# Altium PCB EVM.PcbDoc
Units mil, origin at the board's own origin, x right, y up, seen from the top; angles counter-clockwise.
Board outline 2300 x 3975 mil, 4 copper layers (Top Layer L1, GND Plane L2, Vs Plane L3, Bottom Layer L4), stack 60.668 mil thick; 125 components, 52 nets, 281 pads, 154 vias.
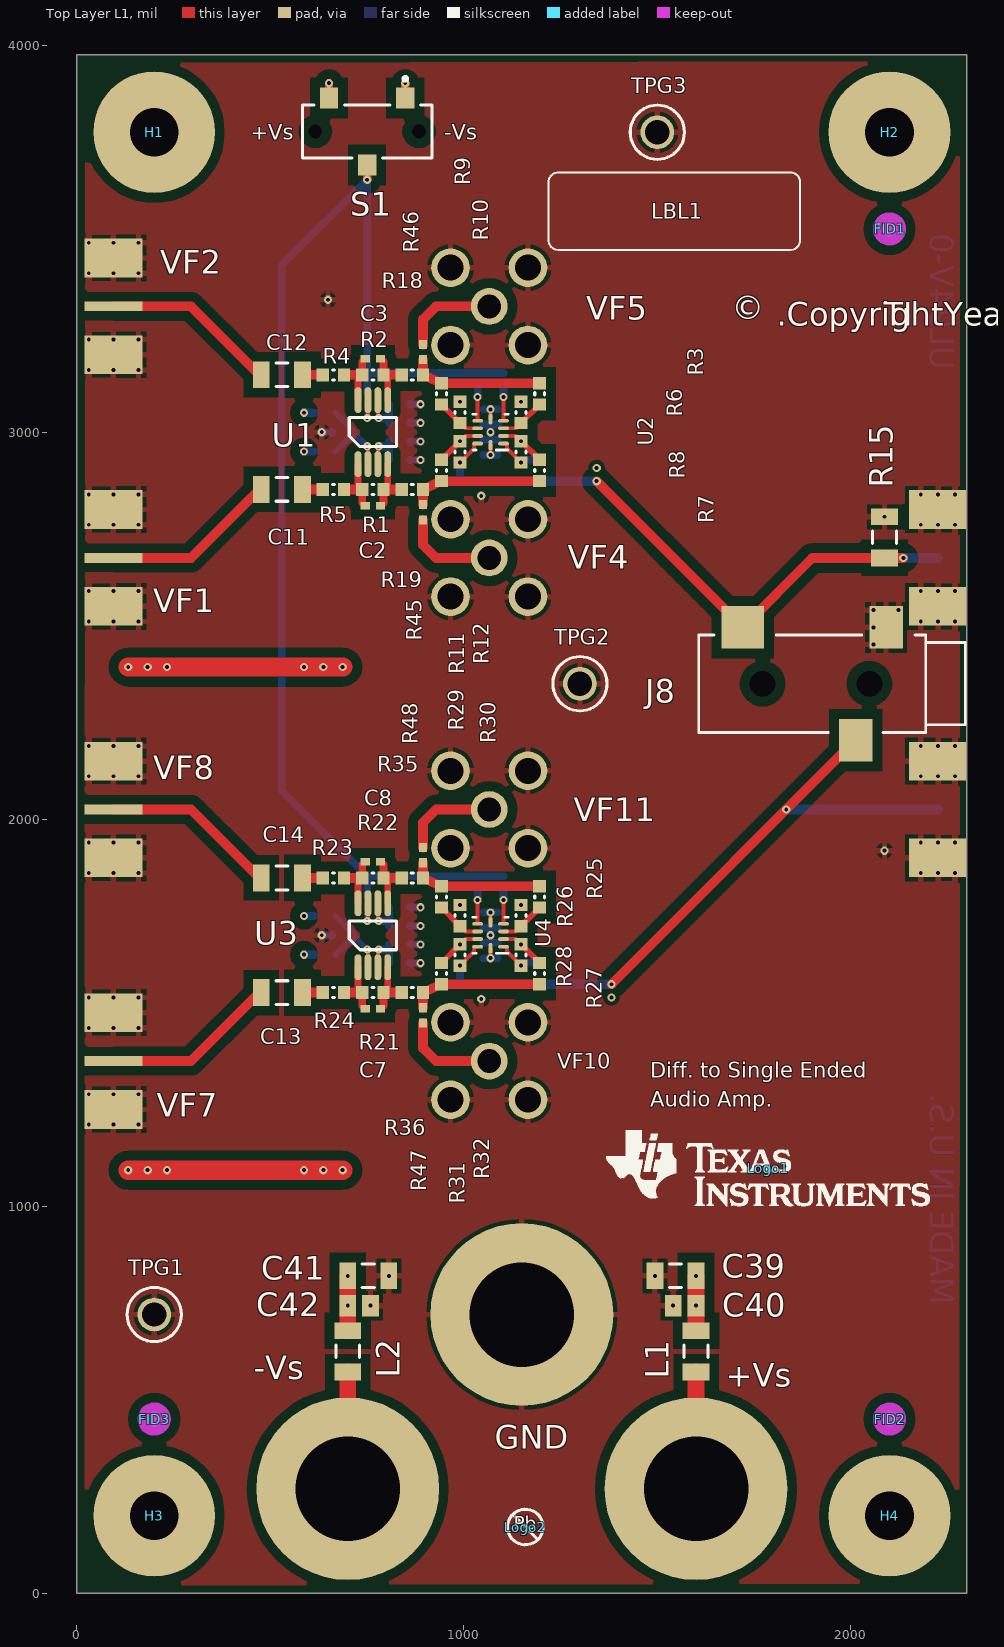
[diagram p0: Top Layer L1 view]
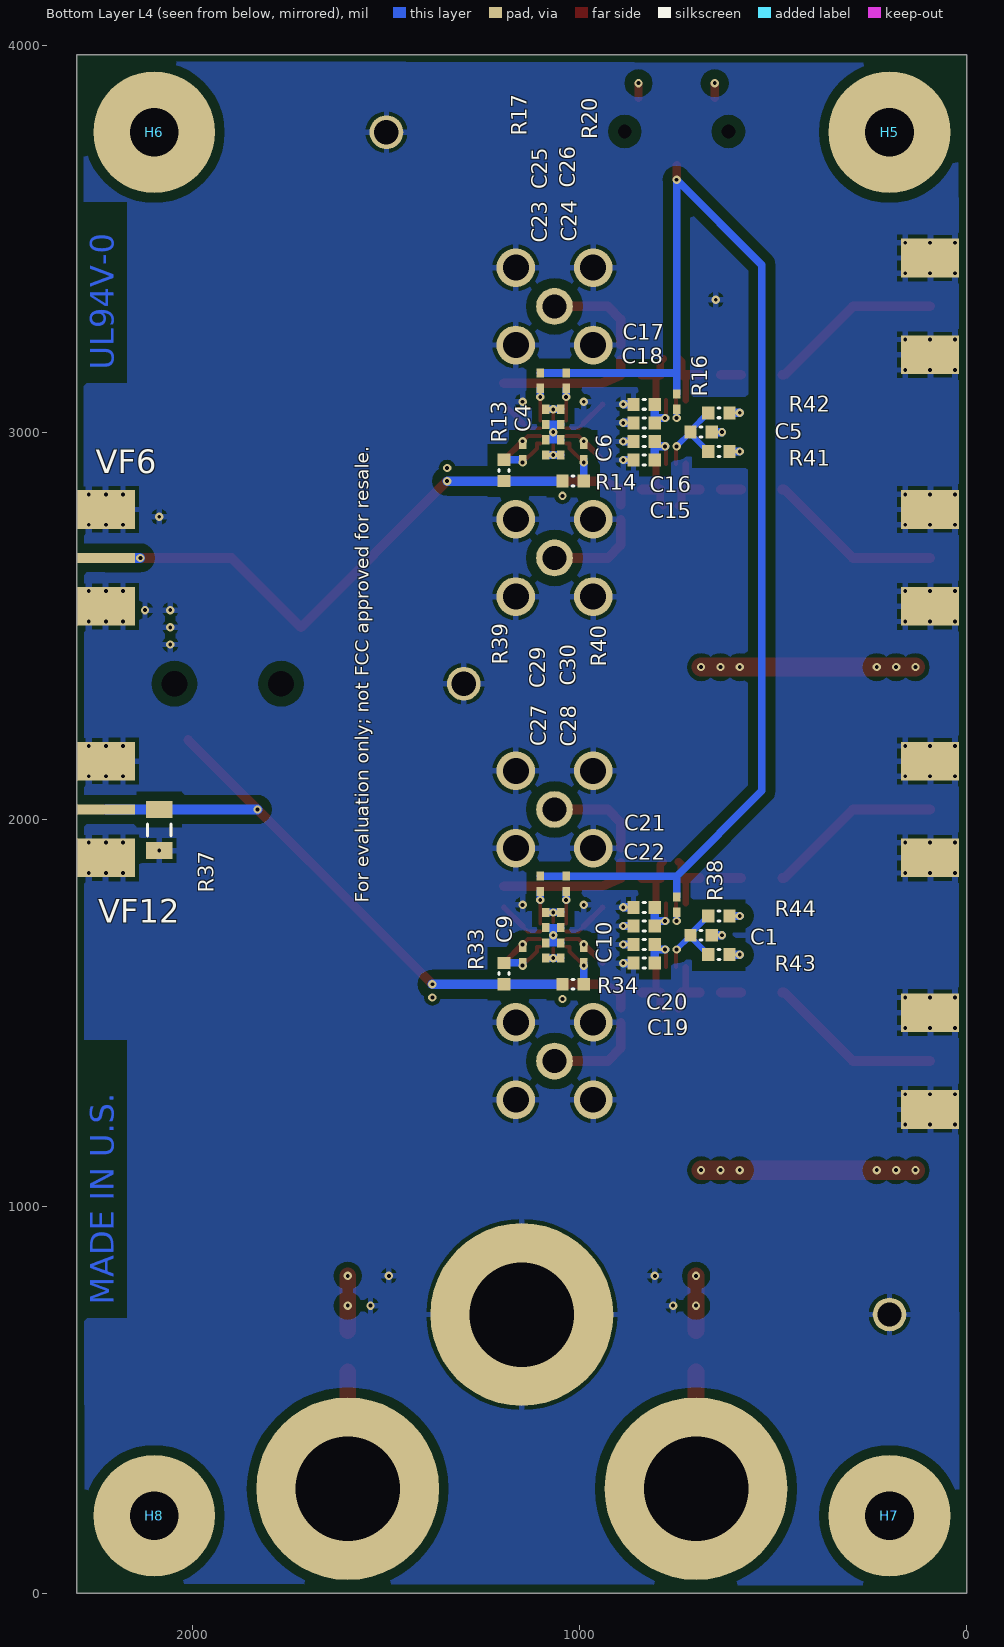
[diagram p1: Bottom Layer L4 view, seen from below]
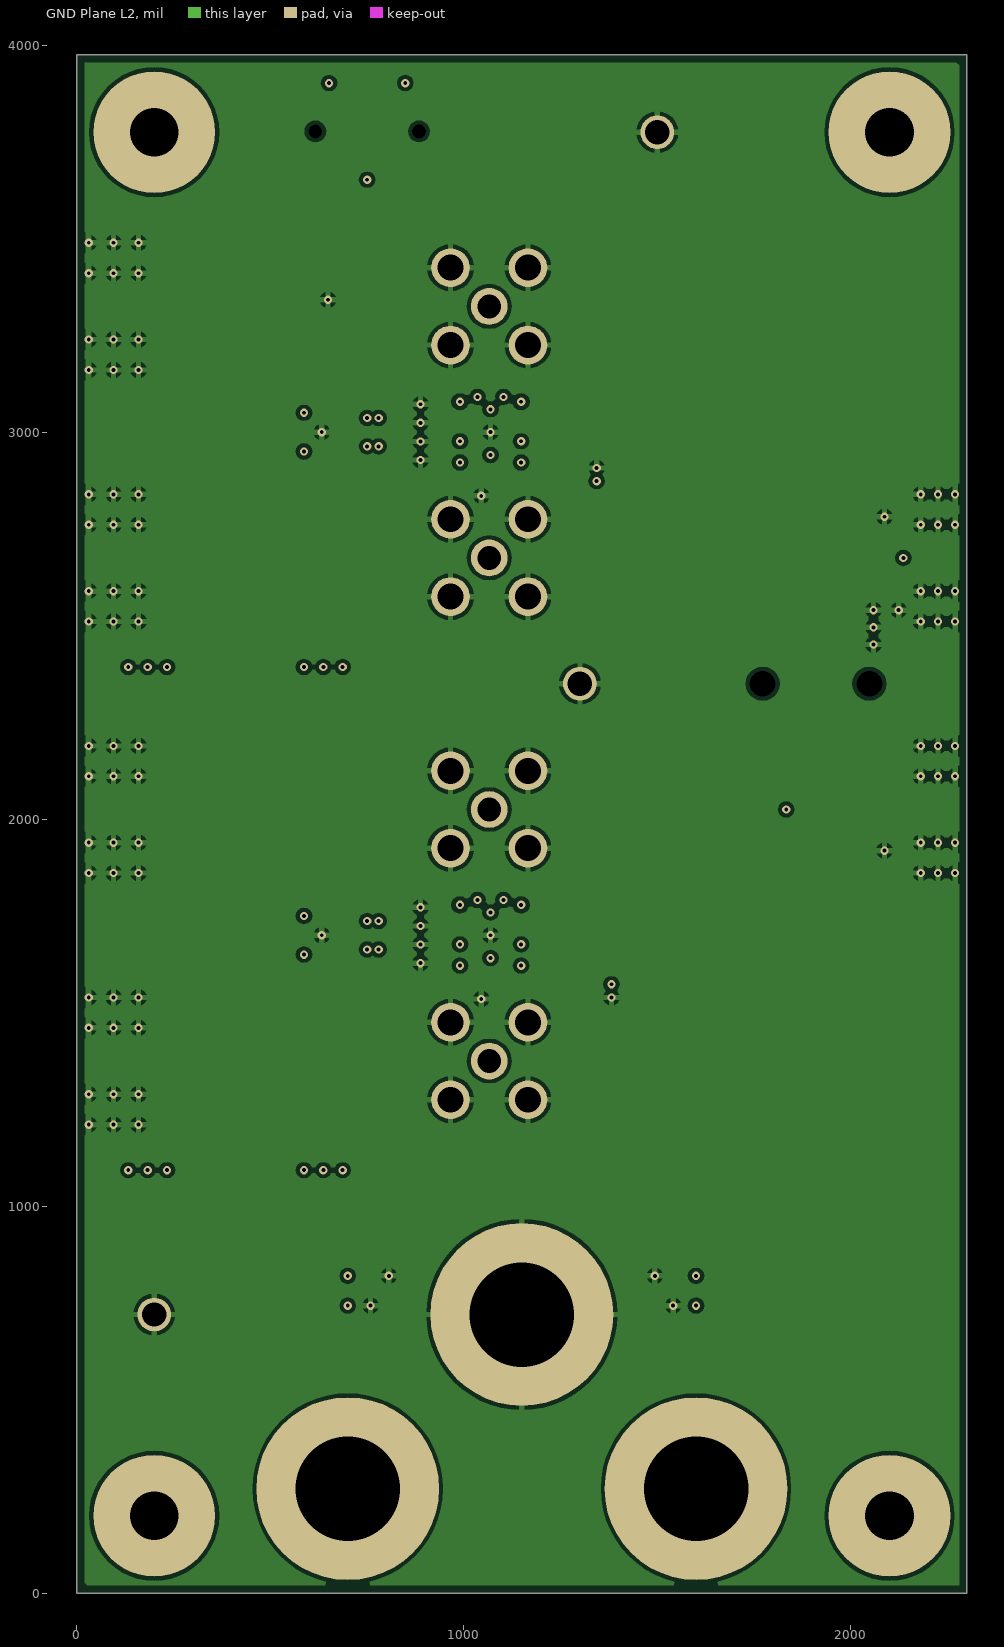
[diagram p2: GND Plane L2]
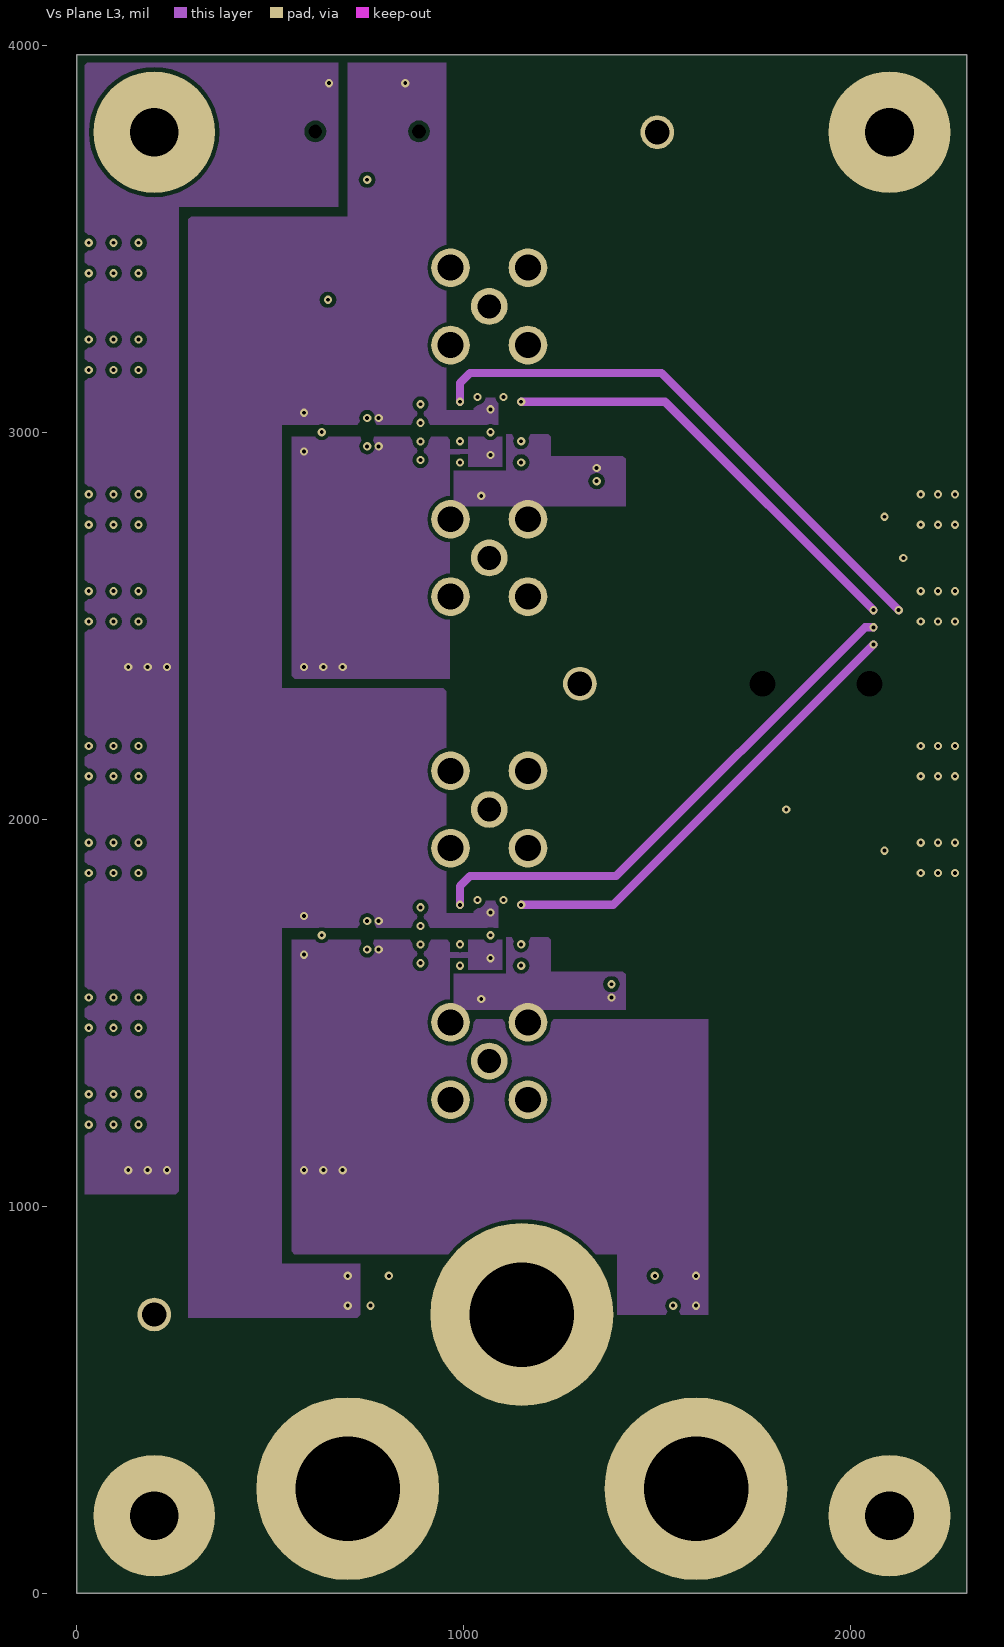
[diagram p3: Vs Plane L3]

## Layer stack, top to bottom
Top Solder: solder mask 0.4, Solder Resist, Dk 3.5
Top Layer L1: signal copper 1.417
Dielectric1: core 15, FR-406, Dk 4.8
GND Plane L2: signal copper 1.417
Dielectric3: prepreg 25, FR-406, Dk 4.2
Vs Plane L3: signal copper 1.417
Dielectric2: core 15, FR-406, Dk 4.2
Bottom Layer L4: signal copper 1.417
Bottom Solder: solder mask 0.4, Solder Resist, Dk 3.5

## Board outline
0,0 2300,0 2300,3975 0,3975

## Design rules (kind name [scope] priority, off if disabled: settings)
AcuteAngle [All] p1: minimum=4.50000000000000E+0001 checktracksonly=FALSE
AssemblyTestPointUsage [All] p1: valid=2
Clearance Clearance_1 [(InNamedPolygon('Top Layer L1-GND') OR InNamedPolygon('Bottom Layer L4-GND'))] p1: gap=25
Clearance Clearance_BoardEdge_MountingHoles [OnCopper and InComponentClass('Mounting Holes') vs IsKeepOut] p2: gap=40
Clearance Clearance_BoardEdge_Poly [OnCopper and InPoly vs IsKeepOut] p3: gap=25
Clearance Clearance_BoardEdge [OnCopper and Not InComponentClass('Logo') and not InComponentClass('FiducialMark') and not InRegion(1000,500,4000,800) and Not IsKeepout vs IsKeepOut] p4: gap=75
Clearance Clearance_Poly [InPolygon] p5: gap=10
Clearance [All] p6: gap=7.87
ComponentClearance ComponentClearance_Shunt [InComponentClass('Header') vs InComponentClass('Shunt')] p1: gap=0 collisioncheckmode=3 verticalgap=0 showdistances=FALSE
ComponentClearance ComponentClearance_MountingHoles_FiducialMarks [InComponentClass('Mounting Holes') vs InComponentClass('FiducialMark')] p2: gap=50 collisioncheckmode=3 verticalgap=10 showdistances=FALSE
ComponentClearance ComponentClearance_Logo [InComponentClass('Logo')] p3: gap=50 collisioncheckmode=3 verticalgap=10 showdistances=FALSE
ComponentClearance ComponentClearance_ScrewToNut [(HasFootprint('NY PMS 440 0025 PH')) vs (HasFootprint('Keystone_1902C'))] p4: gap=5 collisioncheckmode=3 verticalgap=10 showdistances=FALSE
ComponentClearance ComponentClearance_MountingHoles [InComponentClass('Mounting Holes')] p5: gap=125 collisioncheckmode=3 verticalgap=100000 showdistances=FALSE
ComponentClearance ComponentClearance_SmallPassives [HasFootprint('0201*') or HasFootprint('0402*') or HasFootprint('0508') or HasFootprint('0603*') or HasFootprint('0612') or HasFootprint('0805*') or HasFootprint('0815*') or HasFootprint('0830*') or HasFootprint('1206*') or HasFootprint('1210*') or HasFootprint('1808*') or HasFootprint('1812*') or HasFootprint('1825*') or HasFootprint('2010*') or HasFootprint('2220*') or HasFootprint('2225*') or HasFootprint('2512*') or HasFootprint('2728*') or HasFootprint('3518*') or HasFootprint('DGK0008A*') or HasFootprint('RUN0010A*') vs HasFootprint('0201*') or HasFootprint('0402*') or HasFootprint('0508') or HasFootprint('0603*') or HasFootprint('0612') or HasFootprint('0805*') or HasFootprint('0815*') or HasFootprint('0830*') or HasFootprint('1206*') or HasFootprint('1210*') or HasFootprint('1808*') or HasFootprint('1812*') or HasFootprint('1825*') or HasFootprint('2010*') or HasFootprint('2220*') or HasFootprint('2225*') or HasFootprint('2512*') or HasFootprint('2728*') or HasFootprint('3518*') or HasFootprint('DGK0008A*') or HasFootprint('RUN0010A*')] p6: gap=10 collisioncheckmode=3 verticalgap=10 showdistances=FALSE
ComponentClearance ComponentClearance_THtoSMT [IsThruComponent vs IsSMTComponent] p7: gap=30 collisioncheckmode=3 verticalgap=30 showdistances=FALSE
ComponentClearance ComponentClearance_THtoTH [IsThruComponent vs IsThruComponent] p8: gap=118.11 collisioncheckmode=3 verticalgap=30 showdistances=FALSE
ComponentClearance [All] p9: gap=10 collisioncheckmode=3 verticalgap=10 showdistances=FALSE
DiffPairsRouting [All] p1: maxlimit=100 minlimit=10 mostfreqgap=10 toplayer_minwidth=15 toplayer_maxwidth=15 toplayer_prefwidth=15 midlayer1_minwidth=15 midlayer1_maxwidth=15 midlayer1_prefwidth=15 midlayer2_minwidth=15 midlayer2_maxwidth=15 midlayer2_prefwidth=15 bottomlayer_minwidth=15 bottomlayer_maxwidth=15 bottomlayer_prefwidth=15 maxuncoupledlength=1000
FabricationTestPointUsage TestPointUsage [All] p1: valid=2 allowmultiple=FALSE
FabricationTestpoint Testpoint [All] p1: side=3 testpointundercomponent=TRUE minsize=40 maxsize=100 preferedsize=60 minholesize=0 maxholesize=40 preferedholesize=32 testpointgrid=1 allowsidetop=TRUE allowsidebottom=TRUE usegrid=TRUE gridtolerance=0.01
FanoutControl Fanout_LCC [IsLCC] p1: bgadir=Out bgaviamode=Centered fanoutstyle=Auto fanoutdirection=Alternating viagrid=1 // Fanout_LCC (Default Rule)
FanoutControl Fanout_BGA [IsBGA] p2: bgadir=Out bgaviamode=Centered fanoutstyle=Auto fanoutdirection=Alternating viagrid=1 // Fanout_BGA (Default Rule)
FanoutControl Fanout_Default [All] p4: bgadir=Out bgaviamode=Centered fanoutstyle=Auto fanoutdirection=Alternating viagrid=1 // Fanout_Default (Default Rule)
FanoutControl Fanout_Small [(CompPinCount < 5)] p5: bgadir=Out bgaviamode=Centered fanoutstyle=Auto fanoutdirection=OutThenIn viagrid=1 // Fanout_Small (Default Rule)
HoleSize [All] p1: absolutevalues=TRUE maxlimit=270 minlimit=8 maxpercent=80.000 minpercent=20.000
MinimumAnnularRing MinimumAnnularRing_ThermalPadVias [IsVia and InAnyComponent] p1: minimumring=5.91
MinimumAnnularRing [All] p2: minimumring=5.73
MinimumSolderMaskSliver MinimumSolderMaskSliver_Logo [InComponentClass('Logo') vs InComponentClass('Logo')] p1: minsoldermaskwidth=0.7
MinimumSolderMaskSliver [All] p2: minsoldermaskwidth=3.94
PlaneConnect [All] p1: planeconnectstyle=Relief reliefexpansion=10 reliefentries=4 reliefconductorwidth=10 reliefairgap=10
PolygonConnect PolygonConnect_1 [All vs IsNamedPolygon('Vs Plane L3+VS') Or  IsNamedPolygon('Vs Plane L3-VS') Or  IsNamedPolygon('Vs Plane L3+VS')  Or  IsNamedPolygon('Vs Plane GND')] p1: connectstyle=Direct reliefconductorwidth=10 reliefentries=4 polygonreliefangle="90 Angle" airgapwidth=10
PolygonConnect [All] p2: connectstyle=Relief reliefconductorwidth=15 reliefentries=4 polygonreliefangle="90 Angle" airgapwidth=10
RoutingVias ThermalPadVias [IsVia and InAnyComponent] p1: holewidth=7.87 width=19.68 viastyle="Through Hole" minholewidth=7.87 minwidth=19.68 maxholewidth=12.99 maxwidth=23.62
RoutingVias [All] p2: holewidth=16 width=34 viastyle="Through Hole" minholewidth=7.87 minwidth=21.46 maxholewidth=40 maxwidth=65
SMDToCorner [All] p1: distance=30000
SilkToSilkClearance SilkToSilkClearance_Pb-FreeLogo [(HasFootprint('Pb-Free_Overlay_Medium') OR HasFootprint('Pb-Free_Overlay_Small')) vs (HasFootprint('Pb-Free_Overlay_Medium') OR HasFootprint('Pb-Free_Overlay_Small'))] p1: silktosilkclearance=0
SilkToSilkClearance [All] p2: silktosilkclearance=5
SilkToSolderMaskClearance SilkscreenOverComponentPads [IsPad] p1: minsilkscreentomaskgap=5 clearancetoexposedcopper=TRUE
SolderMaskExpansion [All] p1: expansion=1.97
UnpouredPolygon [All] p1: allowunpoured=FALSE
Width [All] p1: maxlimit=100 minlimit=6 preferedwidth=10 checkconnectedcopper=TRUE
15 further rules are at their usual default settings.

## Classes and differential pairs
component class "Mounting Holes": H1 H2 H3 H4
component class Label: LBL1
component class AssemblyNote: ZZ1 ZZ2 ZZ3 ZZ4
component class FiducialMark: FID1 FID2 FID3
component class Logo: Logo1

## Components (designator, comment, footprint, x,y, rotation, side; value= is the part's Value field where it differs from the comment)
+Vs "SPC15363" Tenma_SPC15363 1600,270 r0 top
-Vs "SPC15182" Tenma_SPC15363 700,270 r0 top
C1 "C1608X7R1H104K" 0603L 687,1700 r180 bottom
C2 "" 0402L 765,2810 r180 top
C3 "" 0402L 765,3190 r180 top
C4 "" 0402L 1148,2949 r90 bottom
C5 "C1608X7R1H104K" 0603L 687,3000 r180 bottom
C6 "" 0402L 990,2949 r90 bottom
C7 "" 0402L 765,1510 r180 top
C8 "" 0402L 765,1890 r180 top
C9 "" 0402L 1148,1649 r90 bottom
C10 "" 0402L 990,1649 r90 bottom
C11 "" 1206L 530,2852 r180 top
C12 "" 1206L 530,3148 r180 top
C13 "" 1206L 530,1552 r180 top
C14 "" 1206L 530,1848 r180 top
C15 "C1608C0G1H102J" 0603L 834,2928 r0 bottom
C16 "06035A101JAT2A" 0603L 834,2976 r0 bottom
C17 "C1608C0G1H102J" 0603L 834,3072 r0 bottom
C18 "06035A101JAT2A" 0603L 834,3024 r0 bottom
C19 "C1608C0G1H102J" 0603L 834,1628 r0 bottom
C20 "06035A101JAT2A" 0603L 834,1676 r0 bottom
C21 "C1608C0G1H102J" 0603L 834,1772 r0 bottom
C22 "06035A101JAT2A" 0603L 834,1724 r0 bottom
C23 "C1005C0G1E102J" 0402L 1088,2960.69 r90 bottom
C24 "CC0402JRNPO9BN101" 0402L 1050,2960.69 r90 bottom
C25 "C1005C0G1E102J" 0402L 1088,3039.31 r270 bottom
C26 "CC0402JRNPO9BN101" 0402L 1050,3039.31 r270 bottom
C27 "C1005C0G1E102J" 0402L 1088,1660.68 r90 bottom
C28 "CC0402JRNPO9BN101" 0402L 1050,1660.68 r90 bottom
C29 "C1005C0G1E102J" 0402L 1088,1739.32 r270 bottom
C30 "CC0402JRNPO9BN101" 0402L 1050,1739.32 r270 bottom
C39 "GRM31CR61E106KA12L" 1206L 1546.85,820 r180 top
C40 "08055C104KAT2A" 0805L 1570.47,743 r180 top
C41 "GRM31CR61E106KA12L" 1206L 753.15,820 r180 top
C42 "08055C104KAT2A" 0805L 729.53,743 r180 top
FID1 "Fiducial" Fiducial10-20 2100,3525 r0 top
FID2 "Fiducial" Fiducial10-20 2100,450 r0 top
FID3 "Fiducial" Fiducial10-20 200,450 r0 top
GND "SPC15354" Tenma_SPC15354 1150,720 r180 top
H1 "NY PMS 440 0025 PH" "NY PMS 440 0025 PH" 200,3775 r0 top
H2 "NY PMS 440 0025 PH" "NY PMS 440 0025 PH" 2100,3775 r0 top
H3 "NY PMS 440 0025 PH" "NY PMS 440 0025 PH" 200,200 r0 top
H4 "NY PMS 440 0025 PH" "NY PMS 440 0025 PH" 2100,200 r0 top
H5 "1902C" Keystone_1902C 200,3775 r180 bottom
H6 "1902C" Keystone_1902C 2100,3775 r180 bottom
H7 "1902C" Keystone_1902C 200.36,200 r180 bottom
H8 "1902C" Keystone_1902C 2100.36,200 r180 bottom
J8 "SJ-3523-SMT" CUI_SJ-3523-SMT 1906,2350 r180 top
L1 "LQM31PN1R5MC0L" 1206L 1600,625 r90 top
L2 "LQM31PN1R5MC0L" 1206L 700,625 r90 top
LBL1 "Size: 0.65\" x 0.20 \"" Label_650x200 1544,3571 r0 top
Logo1 "Texas Instruments" TI_Stacked_Overlay_Small 1786,1098 r0 top
Logo2 "Pb-Free Symbol" Pb-Free_Overlay_Small 1159,171 r0 top
Logo3 "FCC disclaimer" FCC_disclaimer 4141,3143 r0 top
R1 "RT0603BRD071K11L" 0603L 765,2852 r0 top
R2 "RT0603BRD071K11L" 0603L 765,3148 r0 top
R3 "RT0603BRD071K11L" 0603L 1196,3099 r270 top
R4 "RT0603BRD07741RL" 0603L 663,3148 r0 top
R5 "RT0603BRD07741RL" 0603L 663,2852 r0 top
R6 "RT0603BRD071K11L" 0603L 1148,3051 r90 top
R7 "RT0603BRD071K11L" 0603L 1196,2901 r90 top
R8 "RT0603BRD071K11L" 0603L 1148,2949 r270 top
R9 "RT0603BRD071K11L" 0603L 942,3099 r270 top
R10 "RT0603BRD071K11L" 0603L 990,3051 r90 top
R11 "RT0603BRD071K11L" 0603L 942,2901 r90 top
R12 "RT0603BRD071K11L" 0603L 990,2949 r270 top
R13 "CRCW06031R00JNEA" 0603L 1196,2901 r270 bottom
R14 "CRCW06031R00JNEA" 0603L 1017.56,2873.44 r0 bottom
R15 "CRCW120632R4FKEA" 1206L 2087,2728.15 r270 top
R16 "CRCW040249R9FKED" 0402L 750.2,3079 r270 bottom
R17 "CRCW040249R9FKED" 0402L 1102.46,3133.23 r270 bottom
R18 "CRCW06030000Z0EA" 0603L 867,3148 r0 top
R19 "CRCW06030000Z0EA" 0603L 867,2852 r0 top
R20 "CRCW040249R9FKED" 0402L 1035.54,3133.23 r270 bottom
R21 "RT0603BRD071K11L" 0603L 765,1552 r0 top
R22 "RT0603BRD071K11L" 0603L 765,1848 r0 top
R23 "RT0603BRD07741RL" 0603L 663,1848 r0 top
R24 "RT0603BRD07741RL" 0603L 663,1552 r0 top
R25 "RT0603BRD071K11L" 0603L 1196,1799 r270 top
R26 "RT0603BRD071K11L" 0603L 1148,1751 r90 top
R27 "RT0603BRD071K11L" 0603L 1196,1601 r90 top
R28 "RT0603BRD071K11L" 0603L 1148,1649 r270 top
R29 "RT0603BRD071K11L" 0603L 942,1799 r270 top
R30 "RT0603BRD071K11L" 0603L 990,1751 r90 top
R31 "RT0603BRD071K11L" 0603L 942,1601 r90 top
R32 "RT0603BRD071K11L" 0603L 990,1649 r270 top
R33 "CRCW06031R00JNEA" 0603L 1196,1601 r270 bottom
R34 "CRCW06031R00JNEA" 0603L 1017.56,1573.44 r0 bottom
R35 "CRCW06030000Z0EA" 0603L 867,1848 r0 top
R36 "CRCW06030000Z0EA" 0603L 867,1552 r0 top
R37 "CRCW120632R4FKEA" 1206L 2087,1971.85 r90 bottom
R38 "CRCW040249R9FKED" 0402L 750.2,1779 r270 bottom
R39 "CRCW040249R9FKED" 0402L 1102.46,1833.23 r270 bottom
R40 "CRCW040249R9FKED" 0402L 1035.54,1833.23 r270 bottom
R41 "RT0603BRD071K11L" 0603L 641,2950 r180 bottom
R42 "RT0603BRD071K11L" 0603L 641,3050 r0 bottom
R43 "RT0603BRD071K11L" 0603L 641,1650 r180 bottom
R44 "RT0603BRD071K11L" 0603L 641,1750 r0 bottom
R45 "CRCW04020000Z0ED" 0402L 894.56,2793 r270 top
R46 "CRCW04020000Z0ED" 0402L 894.56,3207 r270 top
R47 "CRCW04020000Z0ED" 0402L 894.56,1493 r270 top
R48 "CRCW04020000Z0ED" 0402L 894.56,1907 r270 top
S1 "CL-SB-12B-01T" SW_CL-SB-12B-01 750.2,3777 r270 top
TPG1 "5011" Keystone5011 200,720 r0 top
TPG2 "5011" Keystone5011 1300,2350 r0 top
TPG3 "5011" Keystone5011 1500,3775 r0 top
U1 "THS4521IDGK" DGK0008A_N 765,3000 r90 top
U2 "OPA2836IRUNT" RUN0010A 1069,3000 r180 top
U3 "THS4521IDGK" DGK0008A_N 765,1700 r90 top
U4 "OPA2836IRUNT" RUN0010A 1069,1700 r180 top
VF1 "CONN_142-0711-821" CONN_142-0711-821 0,2675 r180 top
VF2 "CONN_142-0711-821" CONN_142-0711-821 0,3325 r180 top
VF4 "142-0701-201" Johnson_142-0701-20x 1065.68,2675 r0 top
VF5 "142-0701-201" Johnson_142-0701-20x 1065.68,3325 r0 top
VF6 "CONN_142-0711-821" CONN_142-0711-821 2320,2675 r0 bottom
VF7 "CONN_142-0711-821" CONN_142-0711-821 0,1375 r180 top
VF8 "CONN_142-0711-821" CONN_142-0711-821 0,2025 r180 top
VF10 "142-0701-201" Johnson_142-0701-20x 1065.68,1375 r180 top
VF11 "142-0701-201" Johnson_142-0701-20x 1065.68,2025 r180 top
VF12 "CONN_142-0711-821" CONN_142-0711-821 2320,2025 r0 bottom
ZZ1 "This Assembly Note is for PCB labels only" AssemblyNoteLabel 185,4438 r0 top
ZZ2 "These assemblies are ESD sensitive, ESD precautions shall be observed." AssemblyNote 185,4354.11 r0 top
ZZ3 "These assemblies must be clean and free from flux and all contaminants. Use of no clean flux is not acceptable." AssemblyNote 185,4265.56 r0 top
ZZ4 "These assemblies must comply with workmanship standards IPC-A-610 Class 2, unless otherwise specified." AssemblyNote 185,4177 r0 top

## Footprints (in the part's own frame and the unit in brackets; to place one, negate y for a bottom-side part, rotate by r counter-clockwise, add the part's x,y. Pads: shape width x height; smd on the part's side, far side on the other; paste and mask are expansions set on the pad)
0402L [mm] "0402 from SM-752 data"
  rect 0.6x0.5 smd: 1(-0.5,0) 2(0.5,0)
  body extent -0.55,-0.3 0.55,0.3, height 0.6
0603L [mm] "0603 from SM-752 data"
  rect 0.8x0.85 smd: 1(-0.7,0) 2(0.7,0)
  silkscreen extent -0.07,-0.33 0.07,0.33, body extent -0.87,-0.47 0.87,0.47, height 0.85
0805L [mm] "0805 from SM-752 data"
  rect 1.1x1.4 smd: 1(-0.75,0) 2(0.75,0)
  body extent -1.1,-0.72 1.1,0.72, height 1.1
1206L [mm] "1206 from SM-752 data"
  rect 1.1x1.75 smd: 1(-1.35,0) 2(1.35,0)
  silkscreen extent -0.4,-0.77 0.4,0.77, body extent -1.7,-0.9 1.7,0.9, height 1.35
AssemblyNote [mil] "Assembly Note"
AssemblyNoteLabel [mil] "Assembly Note for PCB Labels"
CONN_142-0711-821 [mil]
  rect 150x25 smd: 1(-95,0)
  rect 150x100 smd: 2(-95,125) 3(-95,-125)
  rect 150x100 smd far side: 4(-95,125) 5(-95,-125)
CUI_SJ-3523-SMT [mm] "CUI recommended land pattern Rev C CUI_SJ-3523-SMT_Datasheet.pdf"
  rect 2.2x2.8 smd: 1(-4.7,-3.7) 3(-2.7,3.7)
  rect 2.8x2.8 smd: 2(4.7,-3.7)
  round 0 hole 1.7 unplated: 4(-3.6,0) 5(3.4,0)
  silkscreen extent -9.9,-3.2 7.6,3.2, body extent -9.6,-4.5 7.4,4.5, height 5.12
DGK0008A_N [mm] "TSOP, 8-Leads, Body 3x3mm, Pitch 0.65mm, IPC Medium Density"
  oval 1.7x0.45 smd mask+0.05: 1(-2.1,0.975) 2(-2.1,0.325) 3(-2.1,-0.325) 4(-2.1,-0.975) 5(2.1,-0.975) 6(2.1,-0.325) 7(2.1,0.325) 8(2.1,0.975)
  silkscreen extent -0.95,-1.55 0.95,1.55, body extent -2.45,-1.5 2.45,1.5, height 0.94
FCC_disclaimer [mil]
Fiducial10-20 [mm]
  round 1 smd mask+0.5: 1(0,0)
  Top Layer L1 keep-out circle w1.178: c0,0 r0.5
Johnson_142-0701-20x [mil] "Johnson Components recommended land pattern"
  round 95 hole 62: 1(0,0)
  round 100 hole 67: 2(100,100) 3(100,-100) 4(-100,-100) 5(-100,100)
  body extent -156,-156 156,156, height 375
Keystone5011 [mil] "Keystone Multipurpose loops"
  round 87 hole 63: 1(0,0)
  silkscreen extent -70,-70 70,70, body extent -63,-63 63,62, height 319
Keystone_1902C [mil] "Hex Standoff, 4-40 threaded, nylon"
  round 1 on Mech4: 0(0,0)
  body extent -145,-126 146,126, height 501
Label_650x200 [mil] "Thermal Transfer Label"
  silkscreen extent -325,-100 325,100, body extent -326,-101 326,101, height 1
"NY PMS 440 0025 PH" [mm] "4-40 nylon screw and mounting hole"
  round 8 hole 3.2: 1(0,0)
  body extent -3.3,-3.3 3.3,3.3, height 2.69
Pb-Free_Overlay_Small [mil]
  silkscreen extent -46,-46 46,46
RUN0010A [mm]
  oval 0.7x0.25 smd: 1(-0.85,0.75) 2(-0.85,0.25) 3(-0.85,-0.25) 4(-0.85,-0.75) 6(0.85,-0.75) 7(0.85,-0.25) 8(0.85,0.25) 9(0.85,0.75)
  oval 0.25x0.7 smd: 5(0,-0.85) 10(0,0.85)
  silkscreen extent -1.15,-1.17 1.15,1.17, body extent -1.05,-1.05 1.05,1.05, height 0.81
SW_CL-SB-12B-01 [mm] "SMD, 3-Leads, Body 8.5x3.5mm, Pitch 2.5mm"
  rect 1.4x1.2 smd: 1(-2.2,2.5) 2(2.2,0) 3(-2.2,-2.5)
  round 0 hole 0.9 unplated: MH1(0,3.4) MH2(0,-3.4)
  silkscreen extent -3.57,-4.25 1.75,4.25, body extent -1.75,-4.25 1.75,4.25, height 5.5
Tenma_SPC15354 [mm] "Insulated Banana Jack, Black"
  round 12 hole 6.858: 1(0,0)
  body extent -6.3,-6.34 6.35,6.34, height 8.8
Tenma_SPC15363 [mm] "Insulated Banana Jack, Red"
  round 12 hole 6.858: 1(0,0)
  body extent -6.3,-6.34 6.35,6.34, height 8.8
TI_Stacked_Overlay_Small [mil]
  silkscreen extent -418,-98 418,98

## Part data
+Vs: "BANANA JACK, SOLDER LUG, RED, TH"
-Vs: library part SPC15363, "BANANA JACK, SOLDER LUG, GREEN, TH"
C1 C5: "CAP, CERM, 0.1 µF, 50 V, +/- 10%, X7R, 0603"
C2 C3 C4 C6 C7 C8 C9 C10 C11 C12 C13 C14: library part Capacitor, "CAP, CERM, xxxF, xxV, [TempCo], xx%, [PackageReference]"
C15 C17 C19 C21: "CAP, CERM, 1000 pF, 50 V, +/- 5%, C0G/NP0, 0603"
C16 C18 C20 C22: "CAP, CERM, 100 pF, 50 V, +/- 5%, C0G/NP0, 0603"
C23 C25 C27 C29: "CAP, CERM, 1000 pF, 25 V, +/- 5%, C0G/NP0, 0402"
C24 C26 C28 C30: "CAP, CERM, 100 pF, 50 V, +/- 5%, C0G/NP0, 0402"
C39 C41: "CAP, CERM, 10 µF, 25 V, +/- 10%, X5R, 1206"
C40 C42: "CAP, CERM, 0.1 µF, 50 V, +/- 10%, X7R, 0805"
FID1 FID2 FID3: "Fiducial mark.  There is nothing to buy or mount."
GND: "BANANA JACK, SOLDER LUG, BLACK, TH"
H1 H2 H3 H4: "Machine Screw, Round, #4-40 x 1/4, Nylon, Philips panhead"
H5 H6 H7 H8: "Standoff, Hex, 0.5\"L #4-40 Nylon"
J8: "Audio Jack, 3.5mm, Stereo, R/A, SMT"
L1 L2: "Inductor, Multilayer, Ferrite, 1.5 µH, 1 A, 0.17 ohm, SMD"
LBL1: library part THT-14-423-10, "Thermal Transfer Printable Labels, 0.650\" W x 0.200\" H - 10,000 per roll"
Logo1: library part TI_Logo, "Texas Instrument Corporate Signature"
Logo2: library part Pb-Free
Logo3: library part FCC_disclaimer, "FCC_disclaimer"
R1 R2 R3 R6 R7 R8 R9 R10 R11 R12 R21 R22 R25 R26 R27 R28 R29 R30 R31 R32 R41 R42 R43 R44: "RES, 1.11 k, 0.1%, 0.1 W, 0603"
R4 R5 R23 R24: "RES, 741, 0.1%, 0.1 W, 0603"
R13 R14 R33 R34: "RES, 1.0, 5%, 0.1 W, 0603"
R15 R37: "RES, 32.4, 1%, 0.25 W, 1206"
R16 R17 R20 R38 R39 R40: "RES, 49.9, 1%, 0.063 W, 0402"
R18 R19 R35 R36: "RES, 0, 5%, 0.1 W, 0603"
R45 R46 R47 R48: "RES, 0, 5%, 0.063 W, 0402"
S1: "Switch, Slide, SPDT, 0.2A, GULL, 12V, SMD"
TPG1 TPG2 TPG3: "Test Point, Multipurpose, Black, TH"
U1 U3: "VERY LOW POWER, NEGATIVE RAIL INPUT, RAIL-TO-RAIL OUTPUT, FULLY DIFFERENTIAL AMPLIFIER, DGK0008A"
U2 U4: "Dual, Very Low Power, Rail to Rail Out, Negative Rail In, VFB Operational Amplifier, 2.5 to 5.5 V, -40 to 85 degC, 10-pin QFN (RUN0010A), Green (RoHS & no Sb/Br)"
VF1 VF2 VF6 VF7 VF8 VF12: "CONNECTOR, SHEILDED, END LAUNCH JACK, GOLD PLATED, FOR 0.062 PCB, EDGE MOUNTED"
VF4 VF5 VF10 VF11: "Connector, TH, SMA"
ZZ1: library part AssemblyNoteLabel
ZZ2 ZZ3 ZZ4: library part AssemblyNote

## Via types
v1: diameter 21.46, hole 10, Top Layer L1 to Bottom Layer L4, tented both sides, 154 vias

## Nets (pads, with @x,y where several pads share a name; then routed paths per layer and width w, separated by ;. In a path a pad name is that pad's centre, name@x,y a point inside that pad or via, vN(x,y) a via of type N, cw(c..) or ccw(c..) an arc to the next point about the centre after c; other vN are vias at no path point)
+VS: C15.1 C16.1 C19.1 C20.1 C23.1 C24.1 C27.1 C28.1 C39.1 C40.1 L1.2 R41.2 R43.2 S1.3 U1.3 U2.10 U3.3 U4.10 | length 1711
  Top Layer L1 w9.84: v1(1069,1641) U4.10 ; v1(1069,2941) U2.10
  Top Layer L1 w10: U3.3 777.8,1661.32 v1(779.8,1663.32) ; U1.3 777.8,2961.32 v1(779.8,2963.32)
  Top Layer L1 w21.46: S1.3 v1(651.78,3901.91)
  Top Layer L1 w43.31: L1.2 v1(1600,743) v1(1600,820)
  Top Layer L1 w50: v1(133.04,1093) v1(686.96,1093) ; v1(133.04,2393) v1(686.96,2393)
  Bottom Layer L4 w19.68: C28.1 v1(1069,1641) C27.1 ; C24.1 v1(1069,2941) C23.1
  Bottom Layer L4 w21.46: v1(586.96,1650) R43.2 ; v1(586.96,2950) R41.2 ; v1(779.8,1663.32) C20.1@806.44,1663.32 ; v1(779.8,2963.32) C16.1@806.44,2963.32 ; C19.1 C20.1@806.44,1663.32 ; C20.1 C20.1@806.44,1663.32 ; C15.1 C16.1@806.44,2963.32 ; C16.1 C16.1@806.44,2963.32
  other v1: 183.04,1093 233.04,1093 586.96,1093 636.96,1093 183.04,2393 233.04,2393 586.96,2393 636.96,2393
-VS: C17.1 C18.1 C21.1 C22.1 C25.1 C26.1 C29.1 C30.1 C41.2 C42.2 L2.2 R42.1 R44.1 S1.1 U1.6 U2.5 U3.6 U4.5 | length 589
  Top Layer L1 w9.84: U4.5 v1(1069,1759) ; U2.5 v1(1069,3059)
  Top Layer L1 w10: U3.6 777.8,1738.68 v1(779.8,1736.68) ; U1.6 777.8,3038.68 v1(779.8,3036.68)
  Top Layer L1 w21.46: S1.1 v1(848.63,3901.91)
  Top Layer L1 w43.31: L2.2 v1(700,743) v1(700,820)
  Bottom Layer L4 w19.68: C30.1 v1(1069,1759) C29.1 ; C26.1 v1(1069,3059) C25.1
  Bottom Layer L4 w21.46: v1(586.96,1750) R44.1 ; v1(586.96,3050) R42.1 ; v1(779.8,1736.68) 806.44,1736.68 C22.1 ; v1(779.8,3036.68) 806.44,3036.68 C18.1 ; 806.44,1743.73 C21.1 ; 806.44,3043.73 C17.1
GND: C1.2 C5.2 C15.2 C16.2 C17.2 C18.2 C19.2 C20.2 C21.2 C22.2 C23.2 C24.2 C25.2 C26.2 C27.2 C28.2 C29.2 C30.2 C39.2 C40.2 C41.1 C42.1 GND.1 J8.1 R6.2 R10.2 R15.1 R26.2 R30.2 R37.1 TPG1.1 TPG2.1 TPG3.1 VF1.2 VF1.3 VF1.4 VF1.5 VF2.2 VF2.3 VF2.4 VF2.5 VF4.2 VF4.3 VF4.4 VF4.5 VF5.2 VF5.3 VF5.4 VF5.5 VF6.2 VF6.3 VF6.4 VF6.5 VF7.2 VF7.3 VF7.4 VF7.5 VF8.2 VF8.3 VF8.4 VF8.5 VF10.2 VF10.3 VF10.4 VF10.5 VF11.2 VF11.3 VF11.4 VF11.5 VF12.2 VF12.3 VF12.4 VF12.5 | length 5658.5
  Vs Plane L3 w21.46: v1(990,1778.56) 990,1827 1015.91,1852.91 1393.71,1852.91 2036.46,2495.67 v1(2058.46,2495.67) ; v1(990,3078.56) 990,3127 1015.91,3152.91 1510.76,3152.91 v1(2123.61,2540.06) ; v1(1148,1778.56) 1385.74,1778.56 v1(2058.46,2451.28) ; v1(1148,3078.56) 1519.96,3078.56 v1(2058.46,2540.06)
  Bottom Layer L4 w19.68: C28.2 1069,1680.37 ; C30.2 1069,1719.63 ; C24.2 1069,2980.37 ; C26.2 1069,3019.63 ; C27.2 1069,1680.37 ; C29.2 1069,1719.63 ; C23.2 1069,2980.37 ; C25.2 1069,3019.63 ; 1069,1680.37 v1(1069,1700) 1069,1719.63 ; 1069,2980.37 v1(1069,3000) 1069,3019.63
  Bottom Layer L4 w21.46: v1(632.96,1700) C1.2 ; v1(632.96,3000) C5.2 ; C19.2 v1(888.04,1628) ; C20.2 v1(888.04,1676) ; C22.2 v1(888.04,1724) ; C21.2 v1(888.04,1772) ; C15.2 v1(888.04,2928) ; C16.2 v1(888.04,2976) ; C18.2 v1(888.04,3024) ; C17.2 v1(888.04,3072)
  other v1: 759.06,743 1540.95,743 806.3,820 1493.7,820 30.73,1210.73 95,1210.73 159.27,1210.73 30.73,1289.27 95,1289.27 159.27,1289.27 30.73,1460.73 95,1460.73 159.27,1460.73 1045.12,1535.44 30.73,1539.27 95,1539.27 159.27,1539.27 1381.41,1539.44 30.73,1860.73 95,1860.73 159.27,1860.73 2180.73,1860.73 2225,1860.73 2269.27,1860.73 2087,1918.7 30.73,1939.27 95,1939.27 159.27,1939.27 2180.73,1939.27 2225,1939.27 2269.27,1939.27 30.73,2110.73 95,2110.73 159.27,2110.73 2180.73,2110.73 2225,2110.73 2269.27,2110.73 30.73,2189.27 95,2189.27 159.27,2189.27 2180.73,2189.27 2225,2189.27 2269.27,2189.27 30.73,2510.73 95,2510.73 159.27,2510.73 2180.73,2510.73 2225,2510.73 2269.27,2510.73 30.73,2589.27 95,2589.27 159.27,2589.27 2180.73,2589.27 2225,2589.27 2269.27,2589.27 30.73,2760.73 95,2760.73 159.27,2760.73 2180.73,2760.73 2225,2760.73 2269.27,2760.73 2087,2781.3 1045.12,2835.44 30.73,2839.27 95,2839.27 159.27,2839.27 2180.73,2839.27 2225,2839.27 2269.27,2839.27 1343.19,2907.44 30.73,3160.73 95,3160.73 159.27,3160.73 30.73,3239.27 95,3239.27 159.27,3239.27 649,3342 30.73,3410.73 95,3410.73 159.27,3410.73 30.73,3489.27 95,3489.27 159.27,3489.27
Net+Vs_1: +Vs.1 L1.1 | length 301.9
  Top Layer L1 w43.31: +Vs.1 L1.1
Net-Vs_1: -Vs.1 L2.1 | length 301.9
  Top Layer L1 w43.31: -Vs.1 L2.1
NetC1_1: C1.1 R43.1 R44.2 U3.2 | length 236.4
  Top Layer L1 w10: v1(750.2,1663.32) 752.2,1661.32 U3.2
  Bottom Layer L4 w15: R43.1 714.56,1696 C1.1 ; R44.2 714.56,1704 C1.1 ; v1(750.2,1663.32) 714.56,1698.97 C1.1
NetC2_1: C2.1 R1.2 R19.1 U1.4 | length 162
  Top Layer L1 w17.72: R1.2 803.39,2862.83 U1.4
  Top Layer L1 w19.68: C2.1 792.56,2817.87 R1.2
  Top Layer L1 w25: R1.2 R19.1
NetC2_2: C2.2 R1.1 R5.2 U1.1 | length 162
  Top Layer L1 w17.72: U1.1 726.61,2862.83 R1.1
  Top Layer L1 w19.68: R1.1 737.44,2817.87 C2.2
  Top Layer L1 w25: R5.2 R1.1
NetC3_1: C3.1 R2.2 R18.1 U1.5 | length 162
  Top Layer L1 w17.72: R2.2 803.39,3137.17 U1.5
  Top Layer L1 w19.68: C3.1 792.56,3182.13 R2.2
  Top Layer L1 w25: R2.2 R18.1
NetC3_2: C3.2 R2.1 R4.2 U1.8 | length 162
  Top Layer L1 w17.72: U1.8 726.61,3137.17 R2.1
  Top Layer L1 w19.68: R2.1 737.44,3182.13 C3.2
  Top Layer L1 w25: R4.2 R2.1
NetC4_1: C4.1 R8.2 R13.1 U2.1 | length 121.1
  Top Layer L1 w9.84: U2.1 1111.32,2970.47 1111.32,2958.12 v1(1148,2921.44)
  Bottom Layer L4 w19.68: C4.1@1148,2928.56 R13.1
NetC4_2: C4.2 R7.2 R8.1 U2.2 | length 119.1
  Top Layer L1 w9.84: U2.2 1134.4,2990.16 v1(1148,2976.56)
  Top Layer L1 w15: v1(1148,2976.56) R7.2
NetC5_1: C5.1 R41.1 R42.2 U1.2 | length 236.4
  Top Layer L1 w10: v1(750.2,2963.32) 752.2,2961.32 U1.2
  Bottom Layer L4 w15: R41.1 714.56,2996 C5.1 ; R42.2 714.56,3004 C5.1 ; v1(750.2,2963.32) 714.56,2998.97 C5.1
NetC6_1: C6.1 R12.2 R14.1 U2.9 | length 129
  Top Layer L1 w9.84: v1(990,2921.44) 1026.68,2958.12 1026.68,2970.47 U2.9
  Bottom Layer L4 w19.68: R14.1 C6.1
NetC6_2: C6.2 R11.2 R12.1 U2.8 | length 119.1
  Top Layer L1 w9.84: v1(990,2976.56) 1003.6,2990.16 U2.8
  Top Layer L1 w15: R11.2 v1(990,2976.56)
NetC7_1: C7.1 R21.2 R36.1 U3.4 | length 162
  Top Layer L1 w17.72: R21.2 803.39,1562.83 U3.4
  Top Layer L1 w19.68: C7.1 792.56,1517.87 R21.2
  Top Layer L1 w25: R21.2 R36.1
NetC7_2: C7.2 R21.1 R24.2 U3.1 | length 162
  Top Layer L1 w17.72: U3.1 726.61,1562.83 R21.1
  Top Layer L1 w19.68: R21.1 737.44,1517.87 C7.2
  Top Layer L1 w25: R24.2 R21.1
NetC8_1: C8.1 R22.2 R35.1 U3.5 | length 162
  Top Layer L1 w17.72: R22.2 803.39,1837.17 U3.5
  Top Layer L1 w19.68: C8.1 792.56,1882.13 R22.2
  Top Layer L1 w25: R22.2 R35.1
NetC8_2: C8.2 R22.1 R23.2 U3.8 | length 162
  Top Layer L1 w17.72: U3.8 726.61,1837.17 R22.1
  Top Layer L1 w19.68: R22.1 737.44,1882.13 C8.2
  Top Layer L1 w25: R23.2 R22.1
NetC9_1: C9.1 R28.2 R33.1 U4.1 | length 121.1
  Top Layer L1 w9.84: U4.1 1111.32,1670.47 1111.32,1658.12 v1(1148,1621.44)
  Bottom Layer L4 w19.68: C9.1@1148,1628.56 R33.1
NetC9_2: C9.2 R27.2 R28.1 U4.2 | length 119.1
  Top Layer L1 w9.84: U4.2 1134.4,1690.16 v1(1148,1676.56)
  Top Layer L1 w15: v1(1148,1676.56) R27.2
NetC10_1: C10.1 R32.2 R34.1 U4.9 | length 129
  Top Layer L1 w9.84: v1(990,1621.44) 1026.68,1658.12 1026.68,1670.47 U4.9
  Bottom Layer L4 w19.68: R34.1 C10.1
NetC10_2: C10.2 R31.2 R32.1 U4.8 | length 119.1
  Top Layer L1 w9.84: v1(990,1676.56) 1003.6,1690.16 U4.8
  Top Layer L1 w15: R31.2 v1(990,1676.56)
NetC11_1: C11.1 R5.1 | length 52.3
  Top Layer L1 w25: C11.1 R5.1
NetC11_2: C11.2 VF1.1 | length 455.2
  Top Layer L1 w25: VF1.1 295,2675 472,2852 C11.2
NetC12_1: C12.1 R4.1 | length 52.3
  Top Layer L1 w25: C12.1 R4.1
NetC12_2: C12.2 VF2.1 | length 455.2
  Top Layer L1 w25: VF2.1 295,3325 472,3148 C12.2
NetC13_1: C13.1 R24.1 | length 52.3
  Top Layer L1 w25: C13.1 R24.1
NetC13_2: C13.2 VF7.1 | length 455.2
  Top Layer L1 w25: VF7.1 295,1375 472,1552 C13.2
NetC14_1: C14.1 R23.1 | length 52.3
  Top Layer L1 w25: C14.1 R23.1
NetC14_2: C14.2 VF8.1 | length 455.2
  Top Layer L1 w25: VF8.1 295,2025 472,1848 C14.2
NetJ8_2: J8.2 R13.2 R14.2 R15.2 VF6.1 | length 1410.6
  Top Layer L1 w25: v1(1343.19,2873.44) J8.2 1900.29,2675 v1(2135.72,2675)
  Bottom Layer L4 w25: R14.2 v1(1343.19,2873.44) ; v1(2135.72,2675) VF6.1
NetJ8_3: J8.3 R33.2 R34.2 R37.2 VF12.1 | length 1620.5
  Top Layer L1 w25: v1(1381.41,1573.44) J8.3
  Bottom Layer L4 w25: R34.2 v1(1381.41,1573.44) ; v1(1832.97,2025) VF12.1
NetR3_1: R3.1 R9.1 R18.2 R46.2 | length 345.4
  Top Layer L1 w25: R46.2 R18.2 R9.1 R3.1
NetR3_2: R3.2 R6.1 U2.3 | length 119.1
  Top Layer L1 w9.84: U2.3 1134.4,3009.84 R6.1
  Top Layer L1 w15: R6.1 R3.2
NetR7_1: R7.1 R11.1 R19.2 R45.1 | length 345.4
  Top Layer L1 w25: R45.1 R19.2 R11.1 R7.1
NetR9_2: R9.2 R10.1 U2.7 | length 119.1
  Top Layer L1 w9.84: R10.1 1003.6,3009.84 U2.7
  Top Layer L1 w15: R9.2 R10.1
NetR16_1: R16.1 R17.1 R20.1 R38.1 R39.1 R40.1 S1.2 | length 3332.1
  Top Layer L1 w21.46: v1(750.21,3652.09) S1.2
  Bottom Layer L4 w19.68: R38.1 750.2,1852.91 ; R16.1 750.2,3152.91 ; R39.1 R40.1 750.2,1852.91 ; R17.1 R20.1 750.2,3152.91 ; 750.2,1852.91 530,2073.12 530,3431.89 v1(750.21,3652.09) 750.2,3152.91
NetR25_1: R25.1 R29.1 R35.2 R48.2 | length 345.4
  Top Layer L1 w25: R48.2 R35.2 R29.1 R25.1
NetR25_2: R25.2 R26.1 U4.3 | length 119.1
  Top Layer L1 w9.84: U4.3 1134.4,1709.84 R26.1
  Top Layer L1 w15: R26.1 R25.2
NetR27_1: R27.1 R31.1 R36.2 R47.1 | length 345.4
  Top Layer L1 w25: R47.1 R36.2 R31.1 R27.1
NetR29_2: R29.2 R30.1 U4.7 | length 119.1
  Top Layer L1 w9.84: R30.1 1003.6,1709.84 U4.7
  Top Layer L1 w15: R29.2 R30.1
NetR45_2: R45.2 VF4.1 | length 249.9
  Top Layer L1 w25: R45.2 894.56,2708.44 928,2675 VF4.1
NetR46_1: R46.1 VF5.1 | length 249.9
  Top Layer L1 w25: R46.1 894.56,3291.56 928,3325 VF5.1
NetR47_2: R47.2 VF10.1 | length 249.9
  Top Layer L1 w25: R47.2 894.56,1408.44 928,1375 VF10.1
NetR48_1: R48.1 VF11.1 | length 249.9
  Top Layer L1 w25: R48.1 894.56,1991.56 928,2025 VF11.1
PD1: R16.2 U1.7 | length 69.5
  Top Layer L1 w10: v1(750.2,3036.68) 752.2,3038.68 U1.7
  Bottom Layer L4 w15: v1(750.2,3036.68) R16.2
PD2A: R17.2 U2.4 | length 84
  Top Layer L1 w9.84: U2.4 v1(1102.46,3091)
  Bottom Layer L4 w19.68: v1(1102.46,3091) R17.2
PD2B: R20.2 U2.6 | length 84
  Top Layer L1 w9.84: U2.6 v1(1035.54,3091)
  Bottom Layer L4 w19.68: v1(1035.54,3091) R20.2
PD3: R38.2 U3.7 | length 69.5
  Top Layer L1 w10: v1(750.2,1736.68) 752.2,1738.68 U3.7
  Bottom Layer L4 w15: v1(750.2,1736.68) R38.2
PD4A: R39.2 U4.4 | length 84
  Top Layer L1 w9.84: U4.4 v1(1102.46,1791)
  Bottom Layer L4 w19.68: v1(1102.46,1791) R39.2
PD4B: R40.2 U4.6 | length 84
  Top Layer L1 w9.84: U4.6 v1(1035.54,1791)
  Bottom Layer L4 w19.68: v1(1035.54,1791) R40.2
pads on no net: FID1.1 FID2.1 FID3.1 H1.1 H2.1 H3.1 H4.1 H5.0 H6.0 H7.0 H8.0 J8.4 J8.5 S1.MH1 S1.MH2

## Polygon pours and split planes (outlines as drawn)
GND on GND Plane L2 "GND Plane L2-GND" (solid, remove dead copper, pour order 12): 20,20 2280,20 2280,3955 20,3955
+VS on Vs Plane L3 "Vs Plane L3+VS" (solid, remove dead copper, pour order 18): 20,1031 263,1031 263,3582 675,3582 675,3955 263,3955 20,3955
+VS on Vs Plane L3 "Vs Plane L3+VS" (solid, remove dead copper, pour order 16): 1099,2911 1011,2911 1011,2942.44 964,2942.44 964,2783 964,2719 964,2363 556,2363 556,2988 964,2988 964,2956 1011,2956 1011,2988 1099,2988
GND on Vs Plane L3 "Vs Plane GND" (solid, remove dead copper, pour order 14): 974,2808 1418.3,2808 1418.3,2938 1225,2938 1225,2995 1109,2995 1109,2900 974,2900 974,2900.59
GND on Vs Plane L3 "Vs Plane GND" (solid, remove dead copper, pour order 15): 974,1508 1418.3,1508 1418.3,1606 1225,1606 1225,1695 1109,1695 1109,1600 974,1600 974,1600.59
+VS on Vs Plane L3 "Vs Plane L3+VS" (solid, remove dead copper, pour order 17): 1099,1611 1011,1611 1011,1642.44 964,1642.44 964,1483 1632,1483 1632,719.07 1396,719.07 1396,876 964,876 554.96,876 554.96,1688 964,1688 964,1656 1011,1656 1011,1688 1099,1688
-VS on Vs Plane L3 "Vs Plane L3-VS" (solid, remove dead copper, pour order 13): 288,712 732,712 732,851 530,851 530,1719 1089,1719 1089,1789 1026,1789 1026,1757 954,1757 954,2338 530,2338 530,3019 1089,3019 1089,3089 1026,3089 1026,3057 954,3057 954,3955 700,3955 700,3557 288,3557 288,851
GND on Top Layer L1 "Top Layer L1-GND" (solid, remove dead copper, pour order 11): 20,19.86 2280,24.36 2282,3959 22,3954.5
GND on Bottom Layer L4 "Bottom Layer L4-GND" (solid, remove dead copper, pour order 10): 20,19.86 2280,24.36 2282,3959 22,3954.5

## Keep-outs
Keep-Out Layer:
  text ".Layer_Name" at 577,-858.49 h60

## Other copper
Top Layer L1:
  text ".Layer_Name" at 577,-858.49 h60
Vs Plane L3:
  text ".Layer_Name" at 577,-858.49 h60
GND Plane L2:
  pour cut-out: 1126,1778.56 ccw(c1148,1778.56) 1148,1756.56 ccw(c1148,1778.56) 1170,1778.56 ccw(c1148,1778.56) 1148,1800.56 ccw(c1148,1778.56)
  pour cut-out: 968,1778.56 ccw(c990,1778.56) 990,1756.56 ccw(c990,1778.56) 1012,1778.56 ccw(c990,1778.56) 990,1800.56 ccw(c990,1778.56)
  pour cut-out: 1126,3078.56 ccw(c1148,3078.56) 1148,3056.56 ccw(c1148,3078.56) 1170,3078.56 ccw(c1148,3078.56) 1148,3100.56 ccw(c1148,3078.56)
  pour cut-out: 968,3078.56 ccw(c990,3078.56) 990,3056.56 ccw(c990,3078.56) 1012,3078.56 ccw(c990,3078.56) 990,3100.56 ccw(c990,3078.56)
  text ".Layer_Name" at 577,-858.49 h60
Bottom Layer L4:
  text "UL94V-0" at 2205,3161 h60 r270
  text "MADE IN U.S." at 2205,745 h60 r270
  text ".Layer_Name" at 577,-858.49 h60

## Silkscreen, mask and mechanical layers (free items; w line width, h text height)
Top Overlay:
  text "+Vs" at 449,3756 h40
  text "-Vs" at 949,3756 h40
  text ".CopyrightYear" at 1809,3275 h60
  text "TI" at 2085,3275 h60
  text "©" at 1692,3271.48 h105
  text "Diff. to Single Ended" at 1482,1332 h40
  text "Audio Amp." at 1482,1257 h40
  text ".Layer_Name" at 577,-858.49 h60
Bottom Overlay:
  text ".Layer_Name" at 577,-858.49 h60
Top Paste:
  text ".Layer_Name" at 577,-858.49 h60
Bottom Paste:
  text ".Layer_Name" at 577,-858.49 h60
Top Solder:
  text ".Layer_Name" at 577,-858.49 h60
  text ".Layer_Name" at 577,-858.49 h60
Bottom Solder:
  text ".Layer_Name" at 577,-858.49 h60
Drill Guide:
  text ".Layer_Name" at 577,-858.49 h60
M1 Board Outline:
  the board outline again, w10
  text ".Layer_Name" at 577,-858.49 h60
M2 Board Dimensions:
  rectangle: 125,-410.5 500,-285.5
  rectangle: 0,-285.5 125,-160.5
  lines w7: 0,-285.5 1000,-285.5 ; 125,-410.5 125,-160.5 ; 250,-410.5 250,-160.5 ; 500,-410.5 500,-160.5 ; 750,-410.5 750,-160.5 ; 0,-410.5 0,-160.5 1000,-160.5 1000,-410.5 0,-410.5
  text ".Layer_Name" at 577,-858.49 h60
M3 3D STEP Top:
  text ".Layer_Name" at 577,-858.49 h60
M4 3D STEP Bottom:
  text ".Layer_Name" at 577,-858.49 h60
M5 Assembly Top:
  lines w10: -292,-930.17 6308,-930.17 ; -292,-726.83 6310,-726.83 ; -292,-523.5 -292,-1133.5 3713,-1133.5 6310,-1133.5 6310,-523.5 -291.5,-523.5 -291.5,-1133.5 1284,-1133.5 ; 2173,-1133.5 2173,-523.5 ; 3440,-726.83 3440,-523.5 ; 4280,-726.83 4280,-523.5 ; 4902,-1140 4902,-937.17
  text "COMPONENTS MARKED 'DNP' SHOULD NOT BE POPULATED." at 1153.5,-318.5 h60
  text "ASSEMBLY VARIANT:" at 1153,-434 h60
  text ".VariantName" at 2189,-434 h60
  text "PCB VIEWED FROM TOP SIDE" at -228.5,-655.67 h60
  text "BOARD #:" at 2248,-655.67 h60
  text ".PRJ_Number" at 2793.5,-655.67 h60
  text "REV:" at 3638,-655.67 h60
  text ".PCB_Rev" at 3929.5,-655.67 h60
  text "SVN REV:" at 4476,-655.67 h60
  text ".VersionControl_RevNumber" at 4982,-655.67 h60
  text "IGNORE ->" at -228.5,-858.49 h60
  text "PLOT NAME =" at -228.5,-1064.34 h60
  text ".plot_File_Name" at 577,-1064.34 h60
  text "GENERATED    :" at 2250,-1064.34 h60
  text ".Print_Date" at 3119.5,-1064.34 h60
  text ".Print_Time" at 3848.5,-1064.34 h60
  text "TEXAS INSTRUMENTS" at 5113,-1064.34 h60
M6 Assembly Bottom:
  lines w10: -292.5,-727.33 6309.5,-727.33 ; -290.5,-930.67 6309.5,-930.67 ; 1115.5,-1140.5 1115.5,-937.67 ; 1737.5,-727.33 1737.5,-524 ; 2577.5,-727.33 2577.5,-524 ; 3844.5,-1134 3844.5,-524 ; 4733.5,-1134 6309,-1134 6309,-524 -292.5,-524 -292.5,-1134 2304.5,-1134 6309.5,-1134 6309.5,-524
  text "COMPONENTS MARKED 'DNP' SHOULD NOT BE POPULATED." at 6102,-318 h60
  text ".VariantName" at 5058,-434 h60
  text "ASSEMBLY VARIANT:" at 6097,-434 h60
  text ".VersionControl_RevNumber" at 1035.5,-656.17 h60
  text "SVN REV:" at 1541.5,-656.17 h60
  text ".PCB_Rev" at 2088,-656.17 h60
  text "REV:" at 2379.5,-656.17 h60
  text ".PRJ_Number" at 3224,-656.17 h60
  text "BOARD #:" at 3769.5,-656.17 h60
  text "PCB VIEWED FROM BOTTOM SIDE" at 6246,-656.17 h60
  text "IGNORE ->" at 2547.85,-858.49 h60
  text "TEXAS INSTRUMENTS" at 904.5,-1064.84 h60
  text ".Print_Time" at 2169,-1064.84 h60
  text ".Print_Date" at 2898,-1064.84 h60
  text "GENERATED    :" at 3767.5,-1064.84 h60
  text ".plot_File_Name" at 5440.5,-1064.84 h60
  text "PLOT NAME =" at 6246,-1064.84 h60
M9 Title Sheet:
  drawing of 57 lines, arcs and shapes, not listed
  text "1" at 739.84,8036.5 h70
  text "2" at 3235.5,8036.5 h70
  text "3" at 5724.84,8036.5 h70
  text "4" at 8231.51,8036.5 h70
  text "5" at 10730.5,8036.5 h70
  text "6" at 13235.5,8036.5 h70
  text "A" at -416.5,6893.5 h70
  text "A" at 14383.5,6893.5 h70
  text "B" at -416.5,4513.5 h70
  text "B" at 14383.5,4513.5 h70
  text "C" at -416.5,2138.5 h70
  text "C" at 14383.5,2138.5 h70
  text "PROJECT TITLE:" at 11343.5,277.5 h45
  text ".PRJ_Title" at 11393.5,144.17 h70
  text "DESIGNED FOR:" at 11343.5,-23.5 h45
  text ".PRJ_Customer" at 11393.5,-163.5 h70
  text "D" at -416.5,-231.5 h70
  text "D" at 14383.5,-231.5 h70
  text "FILE NAME:" at 11343.5,-323.5 h45
  text ".PCB_File_Name_No_Path" at 11393.5,-443.5 h70
  text "Texas Instruments (TI) and/or its licensors do not warrant the accuracy or completeness of this specification" at 6374,-605.34 h45
  text "ENGINEER:" at 11343.5,-613.5 h45
  text "LAYOUT BY:" at 12848.5,-613.5 h45
  text "or any information contained therein. TI and/or its licensors do not warrant that this design will meet" at 6329.01,-718 h45
  text ".PRJ_Engineer" at 11393.5,-768.49 h70
  text ".PCB_Layout" at 12899,-768.49 h70
  text "the specifications, will be suitable for your application or fit for any particular purpose, or will operate in" at 6329.01,-830.67 h45
  text ".Layer_Name" at 577,-858.49 h60
  text "ALTIUM DESIGNER VERSION:" at 12848.5,-923.5 h45
  text "an implementation. TI and/or its licensors do not warrant that the design is production worthy. You should" at 6329.01,-943.33 h45
  text "completely validate and test your design implementation to confirm the system functionality for your application." at 6374,-1056 h45
  text ".print_Scale" at 11393.5,-1056.83 h70
  text ".Application_BuildNumber" at 12899,-1056.83 h70
  text "1" at 739.84,-1263.5 h70
  text "2" at 3235.5,-1263.5 h70
  text "3" at 5724.84,-1263.5 h70
  text "4" at 8231.51,-1263.5 h70
  text "5" at 10730.5,-1263.5 h70
  text "6" at 13235.5,-1263.5 h70
M10 Fab Notes:
  drawing of 185 lines, arcs and shapes, not listed
  text "DESIGN INFORMATION" at 12381.02,5910 h60
  text "MIN. TRACK WIDTH:" at 11736.46,5730 h60
  text "8" at 12832.7,5730 h60
  text "MIL" at 12987.46,5730 h60
  text "MIN. CLEARANCE:" at 11736.46,5598 h60
  text "0.2" at 12772.7,5598 h60
  text "mm" at 12987.46,5598 h60
  text "MIN. VIA PAD SIZE:" at 11736.46,5466 h60
  text "21" at 12802.71,5466 h60
  text "MIL" at 12987.46,5466 h60
  text "0.05mm (2MIL)" at 12431.46,5324.29 h60
  text "MINIMUM ANNULAR RING" at 11407.23,5320 h60
  text "EXTERNAL" at 13139.46,5320 h60
  text "PER" at 11607.23,5202 h60
  text "IPC-D-275 CLASS 2 LEVEL C" at 11827.23,5202 h60
  text "MIL, HOLES" at 13315.46,5089.71 h60
  text "+/-" at 12923,5089 h60
  text "+/-" at 13777,5089 h60
  text "REGISTRATION TOLERANCES:" at 11407.23,5084 h60
  text "METAL" at 12607,5084 h60
  text "5" at 13183.2,5084 h60
  text "3" at 14016.2,5084 h60
  text "MIL" at 14132.46,5084 h60
  text "MATERIAL:" at 11332.46,4874.54 h60
  text "FR-4 High Tg" at 12318.9,4734.21 h60
  text "FR-408" at 11753.46,4725.64 h60
  text "X" at 12165.46,4725.64 h60
  text "OTHER" at 13241.46,4725.64 h60
  text "62 MIL (1.6mm) +/-10%" at 12073.56,4562.92 h60
  text "THICKNESS:" at 11407.23,4558.64 h60
  text "X" at 11945.4,4558.64 h60
  text "OTHER" at 13358.46,4558.64 h60
  text "TOLERANCE:" at 11407.23,4400.64 h60
  text "X" at 12246.53,4400.64 h60
  text "ANSI IPC-6012 TYPE 3 CLASS 2" at 12433.48,4400.64 h60
  text "OTHER +/-" at 12433.46,4244.64 h60
  text "BOW & TWIST:" at 11407.23,4087.64 h60
  text "X" at 12246.53,4087.64 h60
  text "ANSI IPC-6012 TYPE 3 CLASS 2" at 12433.48,4087.64 h60
  text "OTHER +/-" at 12433.46,3929.13 h60
  text "DRILLING:" at 11332.46,3790.64 h60
  text "REFERENCE:" at 11407.23,3673.64 h60
  text "X" at 12055.46,3673.64 h60
  text "AS SHOWN" at 12242.46,3673.64 h60
  text "X" at 12956.46,3673.64 h60
  text "NC_DRILL FILES" at 13093.46,3673.64 h60
  text "PTH MIN COPPER THICKNESS:" at 11407.23,3515.64 h60
  text "X" at 12757.46,3515.64 h60
  text "1MIL" at 12894.46,3515.64 h60
  text "OTHER" at 13391.46,3515.64 h60
  text "BOARD FINISH:" at 11332.46,3356.64 h60
  text "SILKSCREEN:" at 11487.68,3238.64 h60
  text "X" at 12436.46,3238.64 h60
  text "TOP" at 12562.46,3238.64 h60
  text "X" at 12946.46,3238.64 h60
  text "BOTTOM" at 13073.46,3238.64 h60
  text "SILKSCREEN COLOR:" at 11487.68,3071.64 h60
  text "X" at 12435.42,3071.64 h60
  text "WHITE" at 12562.46,3071.64 h60
  text "OTHER" at 13073.46,3071.64 h60
  text "SOLDER RESIST COLOR:" at 11487.68,2901.64 h60
  text "X" at 12055.42,2742.44 h60
  text "GREEN" at 12182.46,2742.44 h60
  text "BLUE" at 12773.46,2742.44 h60
  text "OTHER" at 13311.46,2742.44 h60
  text "IMMERSION GOLD (ENIG)" at 12393.46,2553.92 h60
  text "ENEPIG" at 13731,2550.64 h60
  text "SURFACE FINISH:" at 11332.46,2549.64 h60
  text "X" at 12206.51,2549.64 h60
  text "IMM. TIN/SILVER OR EQUIV" at 11662,2392.64 h60
  text "OTHER" at 13093.46,2392.64 h60
  text "ARRAY/PANEL:" at 11332.46,2213.64 h60
  text "CUT AND TRIM PER MECH LAYER 1" at 12393.46,2209.35 h60
  text "N.C. ROUTE" at 12393.46,2057.64 h60
  text "X" at 13072.46,2057.64 h60
  text "V. SCORE" at 13259.46,2057.64 h60
  text "CERTIFICATION:" at 11332.46,1920.64 h60
  text "MATERIALS AND WORKMANSHIP FOR ALL PCBS" at 12057.46,1920.64 h60
  text "TO MEET OR EXCEED THE REQUIREMENTS OF:" at 12057.46,1822.64 h60
  text "X" at 11683.96,1686.13 h60
  text "ANSI IPC-A-600F CLASS ->" at 11822.96,1686.13 h60
  text "X" at 13462.02,1686.13 h60
  text "2" at 13580.96,1686.14 h60
  text "1" at 13265.96,1684.64 h60
  text "3" at 13934.96,1684.64 h60
  text "X" at 11686.02,1526.64 h60
  text "UL 94V-0" at 11822.96,1526.64 h60
  text "X" at 12498.02,1526.64 h60
  text "RoHS" at 12634.96,1526.64 h60
  text "OTHER" at 13279.36,1526.64 h60
  text "PER ORDER" at 13676.42,1526.64 h60
  text "ADDITIONAL REQUIREMENTS:" at 11332.46,1385.64 h60
  text "MICROSECTION:" at 11407.23,1270.64 h60
  text "YES" at 12312.96,1270.64 h60
  text "REQUIRED" at 13174.46,1114.49 h60
  text "BARE BOARD ELEC. TEST:" at 11407.23,1111.64 h60
  text "NONE" at 12712.96,1111.64 h60
  text "X" at 13047.46,1111.64 h60
  text "PER ORDER" at 13766.46,1111.64 h60
  text "MANUFACTURER'S UL:" at 11407.23,954.64 h60
  text "RAIL" at 12572.96,950.35 h60
  text "METAL" at 13064.77,950.35 h60
  text "X" at 13440,950 h60
  text "SILK" at 13576.46,950.35 h60
  text ".Layer_Name" at 577,-858.49 h60
M11 Gerber Information:
  lines w10: -292,-930.17 6308,-930.17 ; -292,-726.83 6310,-726.83 ; -292,-523.5 -292,-1133.5 3713,-1133.5 6310,-1133.5 6310,-523.5 -291.5,-523.5 -291.5,-1133.5 1284,-1133.5 ; 2173,-1133.5 2173,-523.5 ; 3440,-726.83 3440,-523.5 ; 4280,-726.83 4280,-523.5 ; 4902,-1140 4902,-937.17
  text "ALL ARTWORK VIEWED FROM TOP SIDE" at -228.5,-655.67 h60
  text "BOARD #:" at 2248,-655.67 h60
  text ".PRJ_Number" at 2793.5,-655.67 h60
  text "REV:" at 3638,-655.67 h60
  text ".PCB_Rev" at 3929.5,-655.67 h60
  text "SVN REV:" at 4476,-655.67 h60
  text ".VersionControl_RevNumber" at 4982,-655.67 h60
  text "LAYER NAME =" at -228.5,-858.49 h60
  text "PLOT NAME =" at -228.5,-1064.34 h60
  text ".plot_File_Name" at 577,-1064.34 h60
  text "GENERATED    :" at 2250,-1064.34 h60
  text ".Print_Date" at 3119.5,-1064.34 h60
  text ".Print_Time" at 3848.5,-1064.34 h60
  text "TEXAS INSTRUMENTS" at 5113,-1064.34 h60
M12 Stackup:
  lines w5: 11363,7442.25 14213,7442.25 ; 11363,7541.55 14213,7541.55 ; 11303,6070 ccw(c11335,6070) 11335,6038 14241,6038 ccw(c14241,6070) 14273,6070 14273,7875 ccw(c14241,7875) 14241,7907 11335,7907 ccw(c11335,7875) 11303,7875 11303,6070
  text "Layer Stack Up Detail for: EVM.PcbDoc" at 11363,7666.77 h75
  text "Layer" at 11363,7504.55 h23
  text "Gerber" at 11975.82,7504.55 h23
  text "Copper" at 12282.08,7504.55 h23
  text "Dielectric" at 12625.89,7504.55 h23
  text "Dielectric" at 12985.8,7504.55 h23
  text "Dielectric" at 13438.68,7504.55 h23
  text "Dielectric" at 13798.58,7504.55 h23
  text "Name" at 11363,7458.55 h23
  text "Document" at 11975.82,7458.55 h23
  text "Thickness" at 12282.08,7458.55 h23
  text "Height" at 12625.89,7458.55 h23
  text "Material" at 12985.8,7458.55 h23
  text "Constant" at 13438.68,7458.55 h23
  text "Type" at 13798.58,7458.55 h23
  text "Top Solder Mask" at 11363,7339.6 h32
  text "(.GTS)" at 11975.82,7339.6 h32
  text "0.4mil" at 12625.89,7339.6 h32
  text "Solder Resist" at 12985.8,7339.6 h32
  text "3.50" at 13438.68,7339.6 h32
  text "Top Layer L1" at 11363,7139.31 h32
  text "(.GTL)" at 11975.82,7139.31 h32
  text "1.417mil" at 12282.08,7139.31 h32
  text "15mil" at 12625.89,7039.17 h32
  text "FR-406" at 12985.8,7039.17 h32
  text "4.80" at 13438.68,7039.17 h32
  text "Core" at 13798.58,7039.17 h32
  text "GND Plane L2" at 11363,6939.02 h32
  text "(.G1)" at 11975.82,6939.02 h32
  text "1.417mil" at 12282.08,6939.02 h32
  text "25mil" at 12625.89,6838.88 h32
  text "FR-406" at 12985.8,6838.88 h32
  text "4.20" at 13438.68,6838.88 h32
  text "PrePreg" at 13798.58,6838.88 h32
  text "Vs Plane L3" at 11363,6738.73 h32
  text "(.G2)" at 11975.82,6738.73 h32
  text "1.417mil" at 12282.08,6738.73 h32
  text "15mil" at 12625.89,6638.58 h32
  text "FR-406" at 12985.8,6638.58 h32
  text "4.20" at 13438.68,6638.58 h32
  text "Core" at 13798.58,6638.58 h32
  text "Bottom Layer L4" at 11363,6538.44 h32
  text "(.GBL)" at 11975.82,6538.44 h32
  text "1.417mil" at 12282.08,6538.44 h32
  text "Bottom Solder Mask" at 11363,6338.15 h32
  text "(.GBS)" at 11975.82,6338.15 h32
  text "0.4mil" at 12625.89,6338.15 h32
  text "Solder Resist" at 12985.8,6338.15 h32
  text "3.50" at 13438.68,6338.15 h32
  text ".Layer_Name" at 577,-858.49 h60
M13 Component Bodies Top:
  text ".Layer_Name" at 577,-858.49 h60
M14 Component Bodies Bottom:
  text ".Layer_Name" at 577,-858.49 h60
M15 Courtyards Top:
  text ".Layer_Name" at 577,-858.49 h60
M16 Courtyards Bottom:
  text ".Layer_Name" at 577,-858.49 h60
Drill Drawing:
  text ".legend" at 5122.5,725.5 h60
  text "Drill Table" at 5147.5,540.5 h60
  text ".Layer_Name" at 577,-858.49 h60

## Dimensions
0,-410.5 to 1000,-410.5 on M2 Board Dimensions
0,0 to 2300,0 on M2 Board Dimensions
0,0 to 0,3975 on M2 Board Dimensions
